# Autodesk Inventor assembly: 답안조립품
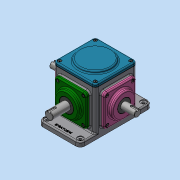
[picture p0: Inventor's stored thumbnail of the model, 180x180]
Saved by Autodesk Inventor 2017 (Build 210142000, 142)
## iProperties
Part Number: 답안조립품
Material: 일반
Document SubType Name: Assembly
Designer: MRC
Author: MRC
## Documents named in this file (16)
- C:\Users\MRC\Desktop\620307V1002\답안조립품.iam
- C:\Users\MRC\Desktop\620307V1002\본체.ipt
- C:\Users\MRC\Desktop\620307V1002\개스킷.ipt
- C:\Users\MRC\Desktop\620307V1002\메인베벨기어.ipt
- C:\Users\MRC\Desktop\620307V1002\메인축.ipt
- C:\Users\MRC\Desktop\620307V1002\메인커버.ipt
- C:\Users\MRC\Desktop\620307V1002\베어링 6203.ipt
- C:\Users\MRC\Desktop\620307V1002\베어링 6204.ipt
- C:\Users\MRC\Desktop\620307V1002\볼트 M4.ipt
- C:\Users\MRC\Desktop\620307V1002\상부커버.ipt
- C:\Users\MRC\Desktop\620307V1002\서브베벨기어.ipt
- C:\Users\MRC\Desktop\620307V1002\서브축.ipt
- C:\Users\MRC\Desktop\620307V1002\서브커버.ipt
- C:\Users\MRC\Desktop\620307V1002\오일 실 17 32 8.ipt
- C:\Users\MRC\Desktop\620307V1002\오일 실 20 35 8.ipt
- C:\Users\MRC\Desktop\620307V1002\키 4x4.ipt
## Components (1 placed, 1 different names)
1. 개스킷:1
